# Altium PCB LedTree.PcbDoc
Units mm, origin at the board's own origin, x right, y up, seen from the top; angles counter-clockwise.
Board outline 80 x 50 mm, 2 copper layers (Top Layer, Bottom Layer); 57 components, 47 nets, 163 pads, 22 vias.
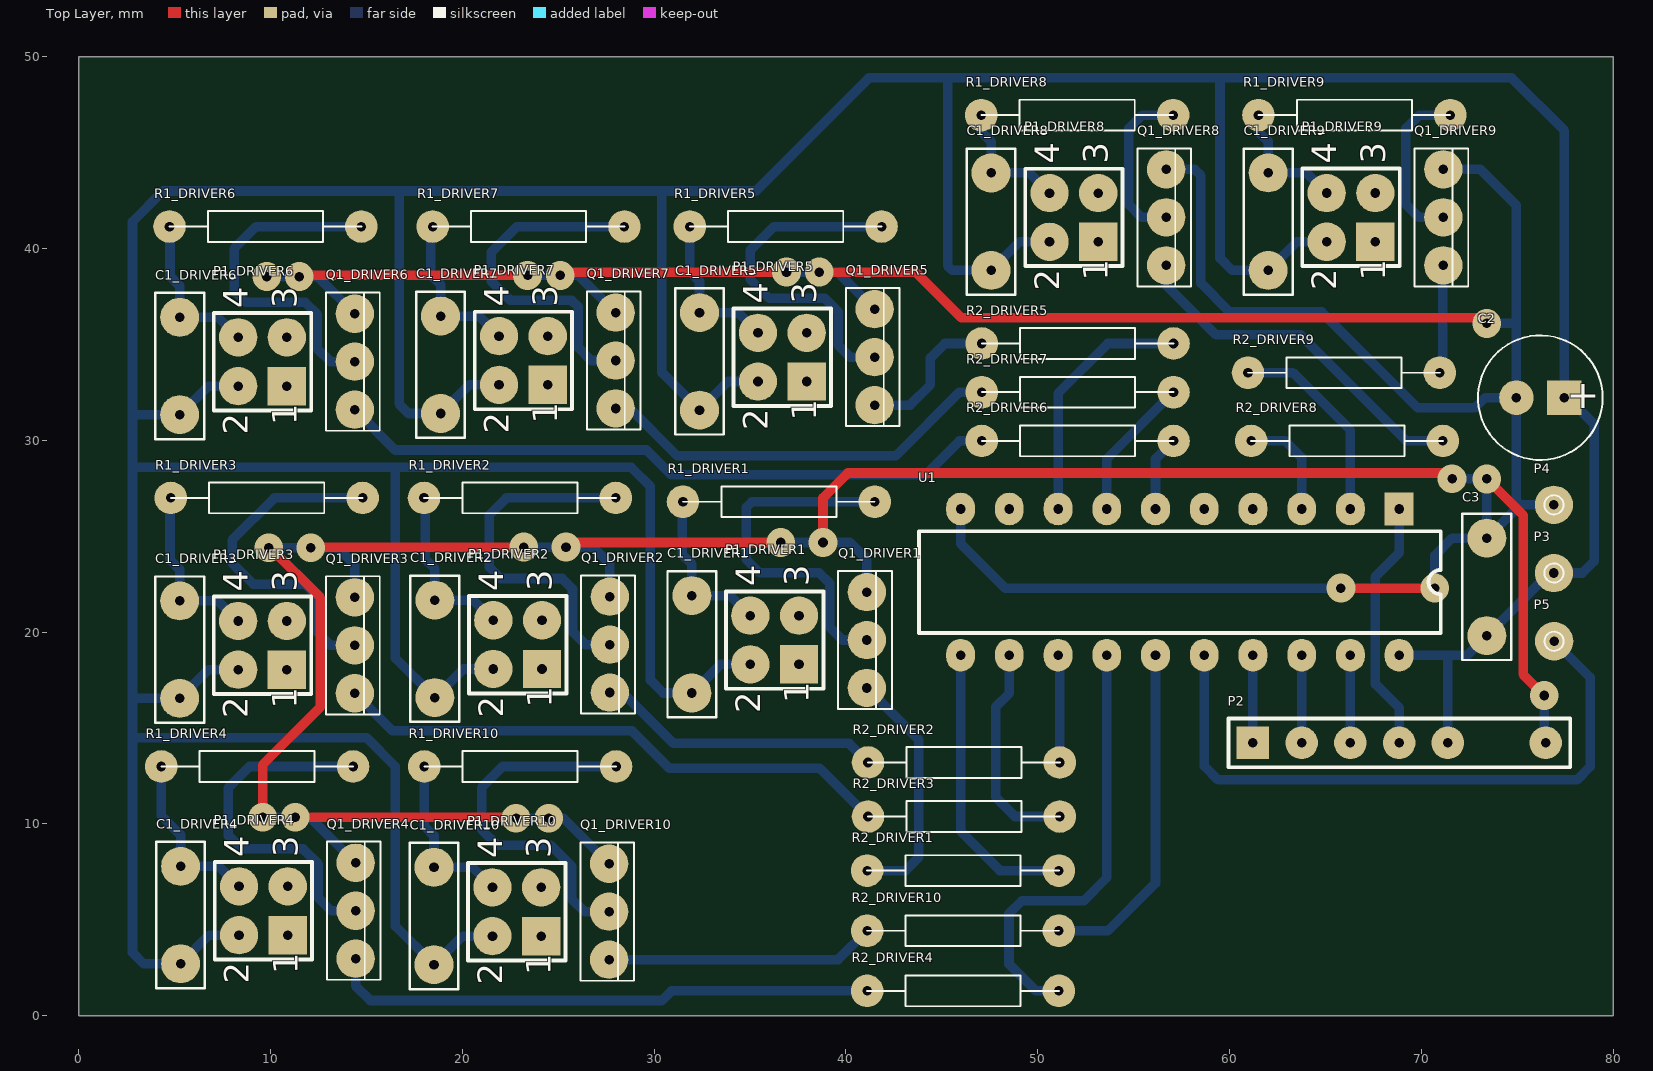
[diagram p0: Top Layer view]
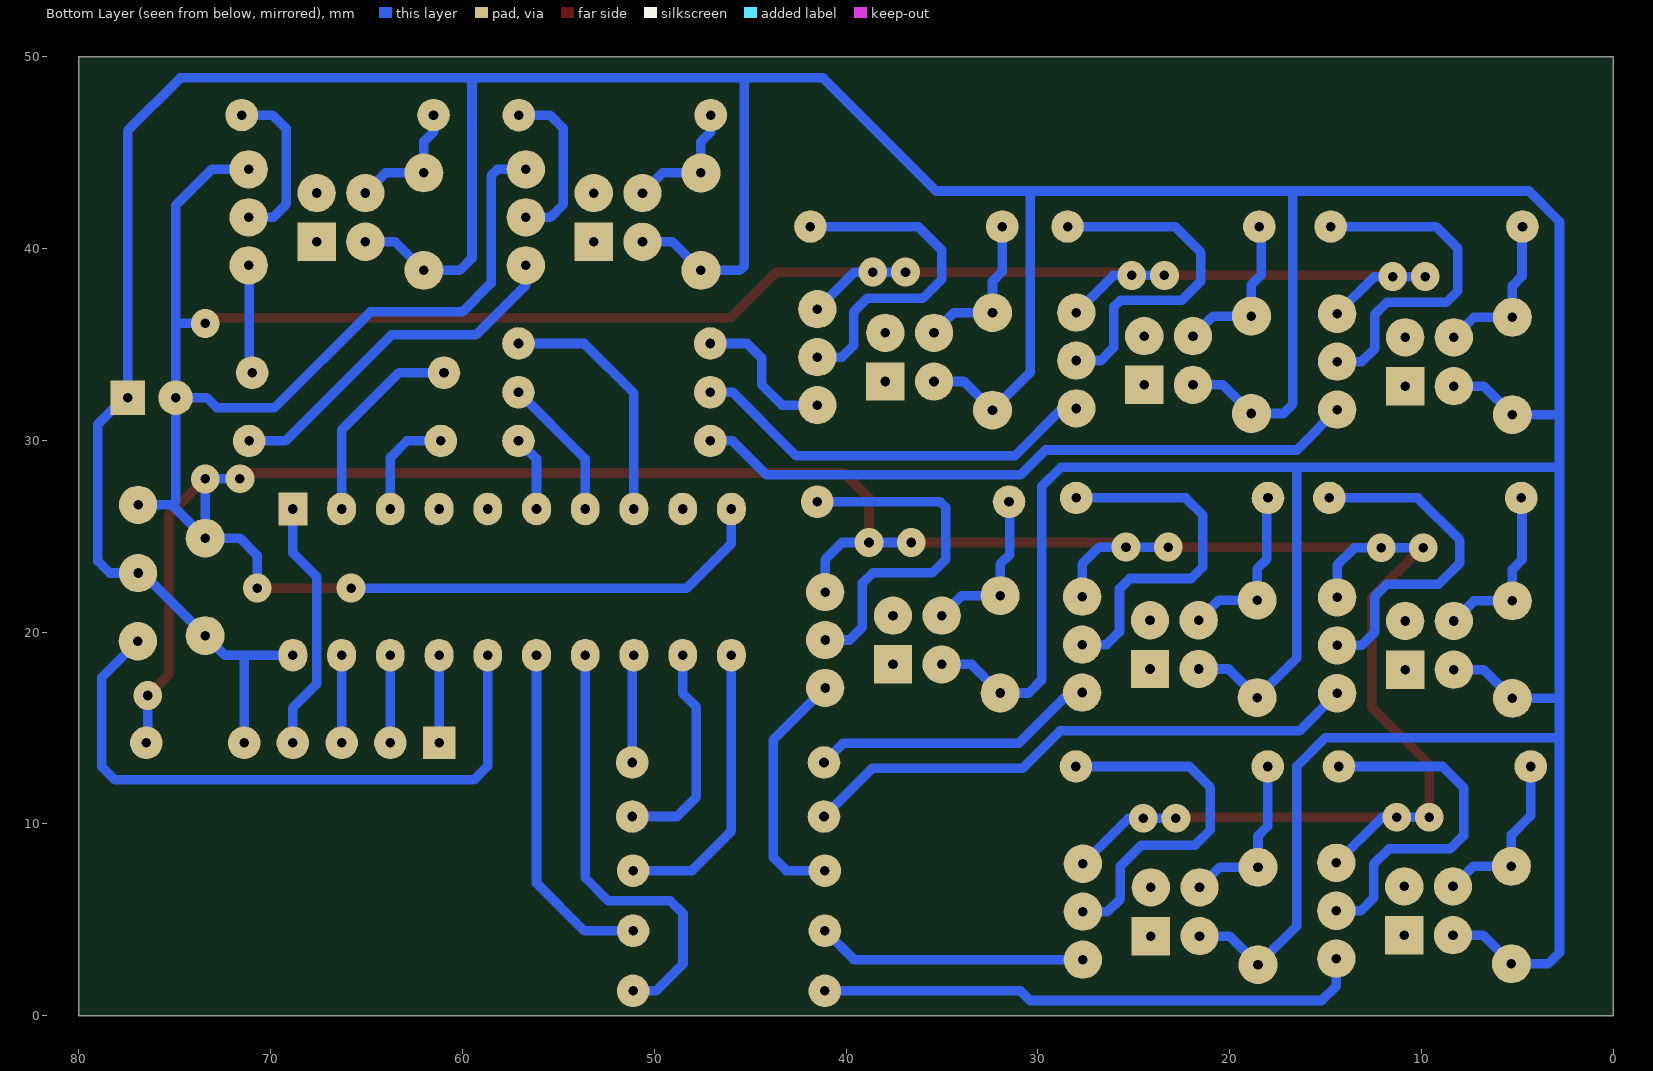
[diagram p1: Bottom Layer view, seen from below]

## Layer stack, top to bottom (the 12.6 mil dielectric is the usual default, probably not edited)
Top Layer: signal copper 0.0356
Dielectric: dielectric 0.32, FR-4, Dk 4.8
Bottom Layer: signal copper 0.0356

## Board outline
0,0 80,0 80,50 0,50

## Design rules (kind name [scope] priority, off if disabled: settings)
Clearance "GND Polygon" [InNet('GND') And InPolygon] p1: gap=1
Clearance [All] p2: gap=0.2
ComponentClearance [All] p1: gap=0.2 collisioncheckmode=3 verticalgap=2540 showdistances=FALSE
Height [All] p1: minheight=0 maxheight=100 prefheight=12.7
HoleSize [All] p1: absolutevalues=TRUE maxlimit=5 minlimit=0.5 maxpercent=80.000 minpercent=20.000
HoleSize Testpoint [All] p2: absolutevalues=TRUE maxlimit=2.54 minlimit=0.025 maxpercent=80.000 minpercent=20.000
HoleSize TestPointUsage [All] p3: absolutevalues=TRUE maxlimit=2.54 minlimit=0.025 maxpercent=80.000 minpercent=20.000
MinimumSolderMaskSliver [All] p1: minsoldermaskwidth=0
NetAntennae [All and not InNet('GND')] p1: netantennaetolerance=0
PlaneClearance [All] p1: clearance=1
PolygonConnect [All] p1: connectstyle=Relief reliefconductorwidth=1 reliefentries=4 polygonreliefangle="90 Angle"
RoutingVias [All] p1: holewidth=0.5 width=1.5 viastyle="Through Hole" minholewidth=0.5 minwidth=1.5 maxholewidth=0.5 maxwidth=1.5
SilkToSilkClearance [All] p1: silktosilkclearance=0
SilkscreenOverComponentPads [All] p1: minsilkscreentomaskgap=0
SolderMaskExpansion [All] p1: expansion=0.102
Width [All] p1: maxlimit=2 minlimit=0.3 preferedwidth=0.5
20 further rules are at their usual default settings.

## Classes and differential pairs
channel class driver: DRIVER1 DRIVER2 DRIVER3 DRIVER4 DRIVER5 DRIVER6 DRIVER7 DRIVER8 DRIVER9 DRIVER10
net class INPUT[1..10]: INPUT1 INPUT2 INPUT3 INPUT4 INPUT5 INPUT6 INPUT7 INPUT8 INPUT9 INPUT10

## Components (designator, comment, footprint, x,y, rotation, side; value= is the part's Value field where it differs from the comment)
C1_DRIVER1 "C_Pinned" CK05 31.963,21.909 r270 top (schematic designator C1)
C1_DRIVER2 "C_Pinned" CK05 18.563,21.671 r270 top (schematic designator C1)
C1_DRIVER3 "C_Pinned" CK05 5.263,21.633 r270 top (schematic designator C1)
C1_DRIVER4 "C_Pinned" CK05 5.308,7.794 r270 top (schematic designator C1)
C1_DRIVER5 "C_Pinned" CK05 32.363,36.657 r270 top (schematic designator C1)
C1_DRIVER6 "C_Pinned" CK05 5.263,36.419 r270 top (schematic designator C1)
C1_DRIVER7 "C_Pinned" CK05 18.863,36.481 r270 top (schematic designator C1)
C1_DRIVER8 "C_Pinned" CK05 47.563,43.943 r270 top (schematic designator C1)
C1_DRIVER9 "C_Pinned" CK05 62.012,43.945 r270 top (schematic designator C1)
C1_DRIVER10 "C_Pinned" CK05 18.52,7.745 r270 top (schematic designator C1)
C2 "CE_Pinned" "ELECTROLYTIC 2.5*6.5" 76.2,32.228 r180 top
C3 "C_Pinned" CK05 73.408,24.9 r270 top
P1_DRIVER1 "Header 2X2" HDR2X2 37.551,18.32 r90 top (schematic designator P1)
P1_DRIVER2 "Header 2X2" HDR2X2 24.151,18.082 r90 top (schematic designator P1)
P1_DRIVER3 "Header 2X2" HDR2X2 10.851,18.044 r90 top (schematic designator P1)
P1_DRIVER4 "Header 2X2" HDR2X2 10.896,4.206 r90 top (schematic designator P1)
P1_DRIVER5 "Header 2X2" HDR2X2 37.951,33.068 r90 top (schematic designator P1)
P1_DRIVER6 "Header 2X2" HDR2X2 10.851,32.83 r90 top (schematic designator P1)
P1_DRIVER7 "Header 2X2" HDR2X2 24.451,32.892 r90 top (schematic designator P1)
P1_DRIVER8 "Header 2X2" HDR2X2 53.151,40.354 r90 top (schematic designator P1)
P1_DRIVER9 "Header 2X2" HDR2X2 67.6,40.356 r90 top (schematic designator P1)
P1_DRIVER10 "Header 2X2" HDR2X2 24.108,4.156 r90 top (schematic designator P1)
P2 "AVR_DEBUGWIRE" AVR_ISP 61.216,14.232 r0 top
P3 "5V" "Pin 2.0x0.5" 76.908,23.084 r90 top
P4 "GND" "Pin 2.0x0.5" 76.908,26.64 r90 top
P5 "BUTTON" "Pin 2.0x0.5" 76.916,19.528 r90 top
Q1_DRIVER1 "KT315" KT-13 39.591,23.192 r270 top (schematic designator Q1)
Q1_DRIVER2 "KT315" KT-13 26.191,22.954 r270 top (schematic designator Q1)
Q1_DRIVER3 "KT315" KT-13 12.891,22.916 r270 top (schematic designator Q1)
Q1_DRIVER4 "KT315" KT-13 12.936,9.078 r270 top (schematic designator Q1)
Q1_DRIVER5 "KT315" KT-13 39.991,37.94 r270 top (schematic designator Q1)
Q1_DRIVER6 "KT315" KT-13 12.891,37.702 r270 top (schematic designator Q1)
Q1_DRIVER7 "KT315" KT-13 26.491,37.764 r270 top (schematic designator Q1)
Q1_DRIVER8 "KT315" KT-13 55.191,45.226 r270 top (schematic designator Q1)
Q1_DRIVER9 "KT315" KT-13 69.64,45.228 r270 top (schematic designator Q1)
Q1_DRIVER10 "KT315" KT-13 26.148,9.028 r270 top (schematic designator Q1)
R1_DRIVER1 "R_Pinned" "Axial R 10.0x1.6" 41.5,26.8 r180 top (schematic designator R1)
R1_DRIVER2 "R_Pinned" "Axial R 10.0x1.6" 28,27 r180 top (schematic designator R1)
R1_DRIVER3 "R_Pinned" "Axial R 10.0x1.6" 14.8,27 r180 top (schematic designator R1)
R1_DRIVER4 "R_Pinned" "Axial R 10.0x1.6" 14.3,13 r180 top (schematic designator R1)
R1_DRIVER5 "R_Pinned" "Axial R 10.0x1.6" 41.855,41.148 r180 top (schematic designator R1)
R1_DRIVER6 "R_Pinned" "Axial R 10.0x1.6" 14.732,41.148 r180 top (schematic designator R1)
R1_DRIVER7 "R_Pinned" "Axial R 10.0x1.6" 28.448,41.148 r180 top (schematic designator R1)
R1_DRIVER8 "R_Pinned" "Axial R 10.0x1.6" 57.055,46.958 r180 top (schematic designator R1)
R1_DRIVER9 "R_Pinned" "Axial R 10.0x1.6" 71.504,46.96 r180 top (schematic designator R1)
R1_DRIVER10 "R_Pinned" "Axial R 10.0x1.6" 28.012,13 r180 top (schematic designator R1)
R2_DRIVER1 "R_Pinned" "Axial R 10.0x1.6" 51.1,7.57 r180 top (schematic designator R2)
R2_DRIVER2 "R_Pinned" "Axial R 10.0x1.6" 51.148,13.208 r180 top (schematic designator R2)
R2_DRIVER3 "R_Pinned" "Axial R 10.0x1.6" 51.148,10.389 r180 top (schematic designator R2)
R2_DRIVER4 "R_Pinned" "Axial R 10.0x1.6" 51.1,1.3 r180 top (schematic designator R2)
R2_DRIVER5 "R_Pinned" "Axial R 10.0x1.6" 57.076,35.052 r180 top (schematic designator R2)
R2_DRIVER6 "R_Pinned" "Axial R 10.0x1.6" 57.076,29.972 r180 top (schematic designator R2)
R2_DRIVER7 "R_Pinned" "Axial R 10.0x1.6" 57.076,32.512 r180 top (schematic designator R2)
R2_DRIVER8 "R_Pinned" "Axial R 10.0x1.6" 61.12,29.972 r0 top (schematic designator R2)
R2_DRIVER9 "R_Pinned" "Axial R 10.0x1.6" 60.96,33.528 r0 top (schematic designator R2)
R2_DRIVER10 "R_Pinned" "Axial R 10.0x1.6" 51.1,4.435 r180 top (schematic designator R2)
U1 "AT90S2313-10PC" 20P3 57.406,22.614 r180 top

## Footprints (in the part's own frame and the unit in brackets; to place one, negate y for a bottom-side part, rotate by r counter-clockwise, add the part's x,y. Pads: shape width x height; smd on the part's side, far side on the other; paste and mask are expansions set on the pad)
20P3 [mm] "DIP; 20 Leads; Row Spacing 7.62 mm; Pitch 2.54 mm"
  rect 1.5x1.7 hole 0.5: 1(-11.43,-3.81)
  oval 1.5x1.7 hole 0.5: 2(-8.89,-3.81) 3(-6.35,-3.81) 4(-3.81,-3.81) 5(-1.27,-3.81) 6(1.27,-3.81) 7(3.81,-3.81) 8(6.35,-3.81) 9(8.89,-3.81) 10(11.43,-3.81) 11(11.43,3.81) 12(8.89,3.81) 13(6.35,3.81) 14(3.81,3.81) 15(1.27,3.81) 16(-1.27,3.81) 17(-3.81,3.81) 18(-6.35,3.81) 19(-8.89,3.81) 20(-11.43,3.81)
  silkscreen extent -13.6,-2.65 13.6,2.65
AVR_ISP [mm]
  rect 1.7x1.7 hole 0.5: 1(0,0)
  round 1.7 hole 0.5: 2(2.54,0) 3(5.08,0) 4(7.62,0) 5(10.16,0) 6(15.26,0)
  silkscreen extent -1.27,-1.27 16.54,1.27
"Axial R 10.0x1.6" [mm]
  round 1.7 hole 0.5: 1(0,0) 2(10,0)
  silkscreen extent 0,-0.8 10,0.8
CK05 [mil]
  round 80 hole 19.68: 1(0,0) 2(200,0)
  silkscreen extent -50,-50 250,50
"ELECTROLYTIC 2.5*6.5" [mm]
  rect 1.8x1.8 hole 0.5: 1(-1.25,0)
  round 1.8 hole 0.5: 2(1.25,0)
  silkscreen extent -3.25,-3.25 3.25,3.25
HDR2X2 [mm] "Connector; Header; 2x2 Position"
  rect 2x2 hole 0.5: 1(0,0)
  round 2 hole 0.5: 2(0,2.54) 3(2.54,0) 4(2.54,2.54)
  silkscreen extent -1.27,-1.27 3.81,3.81
KT-13 [mm]
  round 2 hole 0.5: B(6.1,1.5) C(3.6,1.5) E(1.1,1.5)
  silkscreen extent 0,0 7.2,2.8
"Pin 2.0x0.5" [mm]
  round 2 hole 0.5: 1(0,0)
  silkscreen extent -0.5,-0.5 0.5,0.5

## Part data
C1_DRIVER1 C1_DRIVER2 C1_DRIVER3 C1_DRIVER4 C1_DRIVER5 C1_DRIVER6 C1_DRIVER7 C1_DRIVER8 C1_DRIVER9 C1_DRIVER10 C3: "Capacitor"
C2: "Polarized Capacitor"
P1_DRIVER1 P1_DRIVER2 P1_DRIVER3 P1_DRIVER4 P1_DRIVER5 P1_DRIVER6 P1_DRIVER7 P1_DRIVER8 P1_DRIVER9 P1_DRIVER10: "Header, 2-Pin, Dual row"
P2: "Header, 6-Pin"
P3 P4 P5: library part Pin
Q1_DRIVER1 Q1_DRIVER2 Q1_DRIVER3 Q1_DRIVER4 Q1_DRIVER5 Q1_DRIVER6 Q1_DRIVER7 Q1_DRIVER8 Q1_DRIVER9 Q1_DRIVER10: "Cool soviet transisto"
R1_DRIVER1 R1_DRIVER2 R1_DRIVER3 R1_DRIVER4 R1_DRIVER5 R1_DRIVER6 R1_DRIVER7 R1_DRIVER8 R1_DRIVER9 R1_DRIVER10 R2_DRIVER1 R2_DRIVER2 R2_DRIVER3 R2_DRIVER4 R2_DRIVER5 R2_DRIVER6 R2_DRIVER7 R2_DRIVER8 R2_DRIVER9 R2_DRIVER10: "Resistor"
U1: "8-Bit AVR Microcontroller with 2K Bytes of In-System Programmable Flash Memory"

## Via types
v1: diameter 1.5, hole 0.5, Top Layer to Bottom Layer, 22 vias

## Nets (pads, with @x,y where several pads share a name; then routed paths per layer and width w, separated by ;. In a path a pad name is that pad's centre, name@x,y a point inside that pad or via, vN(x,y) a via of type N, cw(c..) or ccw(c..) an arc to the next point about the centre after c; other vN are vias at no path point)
BUTTON: P5.1 U1.16 | length 33.8
  Bottom Layer w0.5: U1.16 58.676,13.024 59.4,12.3 78.1,12.3 78.8,13 78.8,17.644 P5.1
GND: C2.2 C3.1 P2.6 P4.1 Q1_DRIVER1.E Q1_DRIVER2.E Q1_DRIVER3.E Q1_DRIVER4.E Q1_DRIVER5.E Q1_DRIVER6.E Q1_DRIVER7.E Q1_DRIVER8.E Q1_DRIVER9.E Q1_DRIVER10.E U1.10 | length 298.7
  Top Layer w0.5: v1@9.6,10.362 v1(9.588,10.35) 9.588,13.088 12.6,16.1 12.6,21.8 10,24.4 v1(9.9,24.4) ; v1@9.6,38.338 v1(9.8,38.538) ; v1(11.288,10.35) 22.75,10.35 v1(22.8,10.3) ; v1(11.5,38.538) 11.562,38.6 v1(23.4,38.6) v1@23.338,38.538 ; v1(12.1,24.4) 12.138,24.438 v1(23.2,24.438) ; v1(25.1,38.6) 25.276,38.776 v1(36.9,38.776) ; v1(25.4,24.438) 25.638,24.676 v1(36.6,24.676) ; v1(38.6,38.776) 43.624,38.776 46,36.4 73.1,36.4 v1(73.4,36.1) ; v1(38.8,24.676) 38.8,27 40.1,28.3 71.3,28.3 v1(71.6,28) ; v1(65.8,22.3) v1(70.7,22.3) ; v1(73.408,27.992) 75.3,26.1 75.3,17.8 v1(76.4,16.7)
  Bottom Layer w0.5: v1(9.588,10.35) v1(11.288,10.35) 12.064,10.35 Q1_DRIVER4.E ; v1(9.8,38.538) v1(11.5,38.538) 12.455,38.538 Q1_DRIVER6.E ; v1(9.9,24.4) v1(12.1,24.4) 13.5,24.4 14.391,23.509 Q1_DRIVER3.E ; v1(22.8,10.3) v1(24.5,10.3) 25.276,10.3 Q1_DRIVER10.E ; v1(23.2,24.438) v1(25.4,24.438) 26.8,24.438 27.691,23.547 Q1_DRIVER2.E ; v1(23.4,38.6) v1(25.1,38.6) 26.055,38.6 Q1_DRIVER7.E ; v1(36.6,24.676) v1(38.8,24.676) 40.2,24.676 41.091,23.785 Q1_DRIVER1.E ; v1(36.9,38.776) v1(38.6,38.776) 39.555,38.776 Q1_DRIVER5.E ; U1.10 45.976,24.624 48.3,22.3 v1(65.8,22.3) ; Q1_DRIVER8.E 58.174,44.126 58.5,43.8 58.5,38.2 60,36.7 64.8,36.7 69.8,31.7 72.8,31.7 73.328,32.228 C2.2 74.95,36.1 ; v1(70.7,22.3) 70.7,24 71.6,24.9 C3.1 ; Q1_DRIVER9.E 73.072,44.128 74.95,42.25 74.95,36.1 ; v1(71.6,28) 72.8,28 v1@73.408,27.392 ; v1(73.4,36.1) 74.95,36.1 ; v1(73.408,27.992) v1@73.408,27.392 ; C2.2@74.95,31.7 74.95,26.838 75.148,26.64 ; v1(76.4,16.7) 76.4,14.308 P2.6 ; P4.1 75.148,26.64 ; C3.1 v1@73.408,27.392 ; C3.1 75.148,26.64
INPUT1: R2_DRIVER1.1 U1.11 | length 15.2
  Bottom Layer w0.5: U1.11 45.976,9.624 48.03,7.57 R2_DRIVER1.1 R2_DRIVER1.1@51.148,7.57
INPUT2: R2_DRIVER2.1 U1.13 | length 5.6
  Bottom Layer w0.5: U1.13 51.148,18.712 R2_DRIVER2.1
INPUT3: R2_DRIVER3.1 U1.12 | length 11.5
  Bottom Layer w0.5: U1.12 48.516,16.816 47.8,16.1 47.8,11.4 48.811,10.389 R2_DRIVER3.1
INPUT4: R2_DRIVER4.1 U1.14 | length 23.3
  Bottom Layer w0.5: R2_DRIVER4.1 49.9,1.3 48.5,2.7 48.5,5.335 49.165,6 52.397,6 53.596,7.199 U1.14
INPUT5: R2_DRIVER5.1 U1.8 | length 13.1
  Bottom Layer w0.5: U1.8 51.056,32.456 53.652,35.052 R2_DRIVER5.1
INPUT6: R2_DRIVER6.1 U1.6 | length 3.9
  Bottom Layer w0.5: U1.6 56.136,29.032 R2_DRIVER6.1
INPUT7: R2_DRIVER7.1 U1.7 | length 7.5
  Bottom Layer w0.5: U1.7 53.596,29.032 R2_DRIVER7.1
INPUT8: R2_DRIVER8.1 U1.3 | length 5.7
  Bottom Layer w0.5: R2_DRIVER8.1 62.9,29.972 63.756,29.116 U1.3
INPUT9: R2_DRIVER9.1 U1.2 | length 10.7
  Bottom Layer w0.5: R2_DRIVER9.1 63.3,33.528 66.296,30.532 U1.2
INPUT10: R2_DRIVER10.1 U1.15 | length 17.9
  Bottom Layer w0.5: R2_DRIVER10.1 53.651,4.435 56.136,6.92 U1.15
MISO: P2.2 U1.18 | length 4.6
  Bottom Layer w0.5: P2.2 U1.18
MOSI: P2.1 U1.17 | length 4.6
  Bottom Layer w0.5: P2.1 U1.17
NetC1_DRIVER1_1: C1_DRIVER1.1 P1_DRIVER1.4 R1_DRIVER1.2 | length 8.6
  Bottom Layer w0.5: R1_DRIVER1.2 31.455,26.755 31.455,24.052 31.963,23.544 C1_DRIVER1.1 33.962,21.909 P1_DRIVER1.4
NetC1_DRIVER2_1: C1_DRIVER2.1 P1_DRIVER2.4 R1_DRIVER2.2 | length 9
  Bottom Layer w0.5: R1_DRIVER2.2 18.055,26.945 18.055,23.814 18.563,23.306 C1_DRIVER2.1 20.563,21.671 P1_DRIVER2.4
NetC1_DRIVER3_1: C1_DRIVER3.1 P1_DRIVER3.4 R1_DRIVER3.2 | length 9.1
  Bottom Layer w0.5: R1_DRIVER3.2 4.755,26.955 4.755,23.776 5.263,23.268 C1_DRIVER3.1 7.263,21.633 P1_DRIVER3.4
NetC1_DRIVER4_1: C1_DRIVER4.1 P1_DRIVER4.4 R1_DRIVER4.2 | length 9.1
  Bottom Layer w0.5: R1_DRIVER4.2 4.3,10.438 5.308,9.43 C1_DRIVER4.1 7.307,7.794 P1_DRIVER4.4
NetC1_DRIVER5_1: C1_DRIVER5.1 P1_DRIVER5.4 R1_DRIVER5.2 | length 8.2
  Bottom Layer w0.5: R1_DRIVER5.2 31.855,38.8 32.363,38.292 C1_DRIVER5.1 34.362,36.657 P1_DRIVER5.4
NetC1_DRIVER6_1: C1_DRIVER6.1 P1_DRIVER6.4 R1_DRIVER6.2 | length 8.4
  Bottom Layer w0.5: R1_DRIVER6.2 4.755,41.125 4.755,38.562 5.263,38.054 C1_DRIVER6.1 7.262,36.419 P1_DRIVER6.4
NetC1_DRIVER7_1: C1_DRIVER7.1 P1_DRIVER7.4 R1_DRIVER7.2 | length 8.4
  Bottom Layer w0.5: R1_DRIVER7.2 18.355,41.055 18.355,38.624 18.863,38.116 C1_DRIVER7.1 20.863,36.481 P1_DRIVER7.4
NetC1_DRIVER8_1: C1_DRIVER8.1 P1_DRIVER8.4 R1_DRIVER8.2 | length 6.7
  Bottom Layer w0.5: R1_DRIVER8.2 47.055,46.086 47.563,45.578 C1_DRIVER8.1 49.563,43.943 P1_DRIVER8.4
NetC1_DRIVER9_1: C1_DRIVER9.1 P1_DRIVER9.4 R1_DRIVER9.2 | length 6.7
  Bottom Layer w0.5: R1_DRIVER9.2 61.504,46.088 62.012,45.58 C1_DRIVER9.1 64.011,43.945 P1_DRIVER9.4
NetC1_DRIVER10_1: C1_DRIVER10.1 P1_DRIVER10.4 R1_DRIVER10.2 | length 8.9
  Bottom Layer w0.5: R1_DRIVER10.2 18.012,9.888 18.52,9.38 C1_DRIVER10.1 20.519,7.745 P1_DRIVER10.4
NetQ1_DRIVER1_B: Q1_DRIVER1.B R2_DRIVER1.2 | length 13
  Bottom Layer w0.5: R2_DRIVER1.2@41.148,7.57 43.1,7.57 43.8,8.27 43.8,14.383 Q1_DRIVER1.B Q1_DRIVER1.B@41.187,16.996
NetQ1_DRIVER1_C: Q1_DRIVER1.C R1_DRIVER1.1 | length 18.9
  Bottom Layer w0.5: Q1_DRIVER1.C 39.815,19.592 39.143,20.264 39.143,22.557 38.6,23.1 35.5,23.1 34.8,23.8 34.8,26.5 35.1,26.8 R1_DRIVER1.1
NetQ1_DRIVER2_B: Q1_DRIVER2.B R2_DRIVER2.2 | length 15.1
  Bottom Layer w0.5: Q1_DRIVER2.B@27.787,16.758 Q1_DRIVER2.B 28.346,16.854 31,14.2 40.156,14.2 R2_DRIVER2.2
NetQ1_DRIVER2_C: Q1_DRIVER2.C R1_DRIVER2.1 | length 18.9
  Bottom Layer w0.5: Q1_DRIVER2.C 26.415,19.354 25.743,20.026 25.743,22.257 25.2,22.8 22,22.8 21.4,23.4 21.4,26.1 22.3,27 R1_DRIVER2.1
NetQ1_DRIVER3_B: Q1_DRIVER3.B R2_DRIVER3.2 | length 29.6
  Bottom Layer w0.5: Q1_DRIVER3.B@14.487,16.72 Q1_DRIVER3.B 16.354,14.854 28.846,14.854 30.8,12.9 38.637,12.9 R2_DRIVER3.2
NetQ1_DRIVER3_C: Q1_DRIVER3.C R1_DRIVER3.1 | length 18.2
  Bottom Layer w0.5: Q1_DRIVER3.C 13.115,19.316 12.443,19.988 12.443,21.857 11.8,22.5 9.1,22.5 8,23.6 8,24.8 10.2,27 R1_DRIVER3.1
NetQ1_DRIVER4_B: Q1_DRIVER4.B R2_DRIVER4.2 | length 28.7
  Bottom Layer w0.5: Q1_DRIVER4.B@14.532,2.882 Q1_DRIVER4.B 14.436,1.564 15.2,0.8 30.4,0.8 30.9,1.3 R2_DRIVER4.2
NetQ1_DRIVER4_C: Q1_DRIVER4.C R1_DRIVER4.1 | length 18.7
  Bottom Layer w0.5: R1_DRIVER4.1 8.9,13 7.8,11.9 7.8,9.4 8.5,8.7 11.7,8.7 12.488,7.912 12.488,6.15 13.16,5.478 Q1_DRIVER4.C
NetQ1_DRIVER5_B: Q1_DRIVER5.B R2_DRIVER5.2 | length 7.9
  Bottom Layer w0.5: Q1_DRIVER5.B@41.587,31.744 Q1_DRIVER5.B 43.34,31.84 44.4,32.9 44.4,34.3 45.152,35.052 R2_DRIVER5.2
NetQ1_DRIVER5_C: Q1_DRIVER5.C R1_DRIVER5.1 | length 18.1
  Bottom Layer w0.5: Q1_DRIVER5.C 40.215,34.34 39.6,34.955 39.6,36.7 38.9,37.4 36,37.4 35,38.4 35,39.9 36.248,41.148 R1_DRIVER5.1
NetQ1_DRIVER6_B: Q1_DRIVER6.B R2_DRIVER6.2 | length 35
  Bottom Layer w0.5: Q1_DRIVER6.B@14.487,31.506 Q1_DRIVER6.B 16.493,29.5 29.6,29.5 30.9,28.2 44.145,28.2 45.917,29.972 R2_DRIVER6.2
NetQ1_DRIVER6_C: Q1_DRIVER6.C R1_DRIVER6.1 | length 18.2
  Bottom Layer w0.5: Q1_DRIVER6.C 13.115,34.102 12.443,34.774 12.443,36.557 11.8,37.2 8.7,37.2 8.1,37.8 8.1,40 9.248,41.148 R1_DRIVER6.1
NetQ1_DRIVER7_B: Q1_DRIVER7.B R2_DRIVER7.2 | length 21.6
  Bottom Layer w0.5: Q1_DRIVER7.B@28.087,31.568 Q1_DRIVER7.B 28.736,31.664 31.2,29.2 42.6,29.2 45.912,32.512 R2_DRIVER7.2
NetQ1_DRIVER7_C: Q1_DRIVER7.C R1_DRIVER7.1 | length 18.5
  Bottom Layer w0.5: Q1_DRIVER7.C 26.715,34.164 26.043,34.836 26.043,36.957 25.7,37.3 22.5,37.3 21.5,38.3 21.5,39.8 22.848,41.148 R1_DRIVER7.1
NetQ1_DRIVER8_B: Q1_DRIVER8.B R2_DRIVER8.2 | length 19
  Bottom Layer w0.5: Q1_DRIVER8.B@56.787,39.03 Q1_DRIVER8.B 56.691,38.109 59.3,35.5 63.7,35.5 69.228,29.972 R2_DRIVER8.2
NetQ1_DRIVER8_C: Q1_DRIVER8.C R1_DRIVER8.1 | length 8.8
  Bottom Layer w0.5: Q1_DRIVER8.C 55.415,41.626 54.743,42.298 54.743,46.258 55.443,46.958 R1_DRIVER8.1
NetQ1_DRIVER9_B: Q1_DRIVER9.B R2_DRIVER9.2 | length 5.7
  Bottom Layer w0.5: R2_DRIVER9.2@71.12,33.528 71.12,39.108 Q1_DRIVER9.B Q1_DRIVER9.B@71.236,39.032
NetQ1_DRIVER9_C: Q1_DRIVER9.C R1_DRIVER9.1 | length 8.8
  Bottom Layer w0.5: Q1_DRIVER9.C 69.864,41.628 69.192,42.3 69.192,46.26 69.892,46.96 R1_DRIVER9.1
NetQ1_DRIVER10_B: Q1_DRIVER10.B R2_DRIVER10.2 | length 14.2
  Bottom Layer w0.5: Q1_DRIVER10.B@27.744,2.832 Q1_DRIVER10.B 39.593,2.928 R2_DRIVER10.2
NetQ1_DRIVER10_C: Q1_DRIVER10.C R1_DRIVER10.1 | length 19.1
  Bottom Layer w0.5: Q1_DRIVER10.C 26.372,5.428 25.7,6.1 25.7,7.8 24.6,8.9 21.8,8.9 21,9.7 21,11.9 22.1,13 R1_DRIVER10.1
RESET: P2.4 U1.1 | length 13.2
  Bottom Layer w0.5: P2.4 68.836,16.064 67.6,17.3 67.6,22.9 68.836,24.136 U1.1
SCK: P2.3 U1.19 | length 4.6
  Bottom Layer w0.5: P2.3 U1.19
VCC: C1_DRIVER1.2 C1_DRIVER2.2 C1_DRIVER3.2 C1_DRIVER4.2 C1_DRIVER5.2 C1_DRIVER6.2 C1_DRIVER7.2 C1_DRIVER8.2 C1_DRIVER9.2 C1_DRIVER10.2 C2.1 C3.2 P1_DRIVER1.2 P1_DRIVER2.2 P1_DRIVER3.2 P1_DRIVER4.2 P1_DRIVER5.2 P1_DRIVER6.2 P1_DRIVER7.2 P1_DRIVER8.2 P1_DRIVER9.2 P1_DRIVER10.2 P2.5 P3.1 U1.20 | length 329.5
  Bottom Layer w0.5: 2.861,31.339 C1_DRIVER6.2 6.754,32.83 P1_DRIVER6.2 ; P1_DRIVER3.2 6.755,18.044 C1_DRIVER3.2 2.953,16.553 2.8,16.4 ; P1_DRIVER4.2 6.799,4.206 C1_DRIVER4.2 3.386,2.714 2.8,3.3 2.8,14.5 ; 16.5,28.5 16.5,18.654 C1_DRIVER2.2 20.055,18.082 P1_DRIVER2.2 ; P1_DRIVER10.2 20.011,4.156 C1_DRIVER10.2 16.5,4.685 16.5,13 15,14.5 2.8,14.5 ; P1_DRIVER7.2 20.355,32.892 C1_DRIVER7.2 17.199,31.401 16.7,31.9 16.7,43 ; P1_DRIVER1.2 33.454,18.32 C1_DRIVER1.2 30.472,16.829 29.8,17.5 29.8,27.6 28.8,28.6 2.8,28.6 ; P1_DRIVER5.2 33.854,33.068 C1_DRIVER5.2 30.4,33.54 30.4,43 ; P1_DRIVER8.2 49.055,40.354 C1_DRIVER8.2 45.538,38.863 45.3,39.1 45.3,48.9 ; P1_DRIVER9.2 63.503,40.356 C1_DRIVER9.2 60.135,38.865 59.5,39.5 59.5,48.9 ; U1.20 71.376,18.804 ; P2.5 71.376,18.804 ; 2.8,14.5 2.8,16.4 ; 2.8,16.4 2.8,28.6 ; 2.8,28.6 2.8,41.4 4.4,43 16.7,43 ; 16.7,43 30.4,43 ; 30.4,43 35.3,43 41.2,48.9 45.3,48.9 ; 45.3,48.9 59.5,48.9 ; 59.5,48.9 74.7,48.9 77.45,46.15 C2.1 77.618,32.228 79,30.846 79,23.7 78.384,23.084 P3.1 76.672,23.084 C3.2 72.392,18.804 71.376,18.804
pads on no net: P1_DRIVER1.1 P1_DRIVER1.3 P1_DRIVER2.1 P1_DRIVER2.3 P1_DRIVER3.1 P1_DRIVER3.3 P1_DRIVER4.1 P1_DRIVER4.3 P1_DRIVER5.1 P1_DRIVER5.3 P1_DRIVER6.1 P1_DRIVER6.3 P1_DRIVER7.1 P1_DRIVER7.3 P1_DRIVER8.1 P1_DRIVER8.3 P1_DRIVER9.1 P1_DRIVER9.3 P1_DRIVER10.1 P1_DRIVER10.3 U1.4 U1.5 U1.9

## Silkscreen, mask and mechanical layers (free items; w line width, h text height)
outline:
  the board outline again, w0.2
